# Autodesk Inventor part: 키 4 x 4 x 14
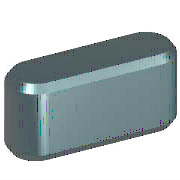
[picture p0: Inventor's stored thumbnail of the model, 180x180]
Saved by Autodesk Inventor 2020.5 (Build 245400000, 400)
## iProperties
IsCustomPart: 1
Created: 2012-02
Part Number: 키 4 x 4 x 14
Material: 강철, 연강
Description: 키 및 해당 키홈
Document SubType Name: Modeling
Standard: KS B 1311
Designer: mduedu
Standards Organization: KS
Language: ko-KR
Size Designation: 4 x 4 x 12
Categories: <MemberInstance><Categories><Category DisplayName="샤프트 부품" InternalName="7f7aeb1f-a693-4053-b835-cee3144e0d98" Mnemonic="SHFT"><Category DisplayName="키" Interna
Density: 1 g/cm^3
Appearance: 노란색
Author: mduedu
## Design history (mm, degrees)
workplane "Work Plane1"
workplane "Work Plane2"
sketch "스케치1"
  geometry: L1 (2, 2)-(12, 2); L2 (12, -2)-(2, -2); L3 (0, 8.8)-(0, -3.8) reference; L4 (-2.4, 0)-(14.4, 0) reference; L5 (14, 0)-(14, 7); A1 r 2 centre (2, 0) between (2, 2) and (2, -2); A2 r 2 centre (12, 0) between (12, -2) and (12, 2)
  constraints: 6 end point, 5 point on circle, 4 tangent, 3 point on line, 2 centre point, 1 horizontal, 1 parallel, 1 perpendicular
  dimensions: "d0" = 2 radius of A1 (= 0.5 x PB); "d13" = 2 radius of A2 (= 0.5 x PB); "d14" = 14 distance between parallel lines of L5 L3 (= NLG)
extrude "본체1" new body sketch "스케치1" taper "d3" = 0 deg; stored distance "d4" = 10
workplane "Work Plane3"
body "Solid1"
chamfer "모따기1" distance "d8" = 0.25 (= PHH); stored, may be unused: second distance "d9" = 0.25 (= PHH), angle "d15" = 45 deg
other parameters: "d1" = -2.5 (= -PNT), "d2" = 1.5 (= PH - PNT), "NLG" = 14 [user parameter; used in 3 equation terms], "PB" = 4 [user parameter; used in 2 equation terms], "PNT" = 2.5 [user parameter; used in 2 equation terms], "PH" = 4 [user parameter; used in 1 equation term], "PHH" = 0.25 [user parameter; used in 2 equation terms], "d10" = 0, "d16" = 0, "d17" = 0, "d18" = 0, "PLB2" = 14 (= NLG) [user parameter], "WDMAX" = 12 [user parameter], "PLB1" = 14 (= NLG) [user parameter], "RR" = 0.08 [user parameter], "PUEB" = 1.8 [user parameter]
